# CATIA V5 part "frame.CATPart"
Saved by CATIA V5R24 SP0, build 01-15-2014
Part number: Frame
Bounding box of the stored display mesh (mm): x -211.5 to 30, y -33.991 to 33.991, z -18 to 268
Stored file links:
  D:\OneDrive\OneDrive - 한양대학교\문서\Teaching\2021\CAD\Final Exam\oscillation motion\frame.CATPart
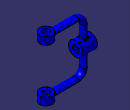
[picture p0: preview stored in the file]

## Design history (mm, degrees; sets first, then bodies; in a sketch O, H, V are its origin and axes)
Body1 (main body)
  Sketch1 on xy-plane, origin (0, 0, 0), H (1, 0, 0), V (0, 1, 0)
    circle A1 centre (0, 0) radius 16
    circle A2 centre (0, 0) radius 30
    radius A2 = 30
    radius A1 = 16
  Pad1: profile Sketch1, direction (0, 0, 1), length 18, mirrored extent
  Plane1: type Offset, RefPlane yz-plane, Offset 20, reversed
  Sketch2 on Plane1, origin (-20, 0, 0), H (0, 1, 0), V (0, 0, 1)
  Sketch3 on Plane1, origin (-20, 0, 0), H (0, 1, 0), V (0, 0, 1)
    ellipse A1 centre (0, 0) semi-axes 17.5, 11 rotation 180
    reference intersected line E1 through (0, 0) direction (-1, 0) from xy-plane
    distance E1 A1 = 11
    "Radius" A1 = 17.5
  Sketch4 on zx-plane, origin (0, 0, 0), H (-1, 0, 0), V (0, 0, 1)
    line L1 (20, 0) -> (141.5, 0)
    point P1 (20, 0)
    reference intersected line E1 through (20, 0) direction (0, -1) from Plane1
    arc A1 centre (141.5, 36) radius 36 from (141.5, 0) to (177.5, 36) ccw
    line L2 (177.5, 36) -> (177.5, 96)
    length L1 = 121.5
    radius A1 = 36
    length L2 = 60
    horizontal: L1 H
    coincidence: E1 P1, L1 H
    tangency: L2 A1
  Rib1: profile Sketch3, centre curve Sketch4
  Plane2: type Offset, RefPlane face of Rib1, Offset 29, reversed
  Sketch5 on zx-plane, origin (0, 0, 0), H (-1, 0, 0), V (0, 0, 1)
    line L1 (211.5, 109) -> (141.5, 109)
    line L2 (141.5, 109) -> (141.5, 91)
    line L3 (141.5, 91) -> (211.5, 91)
    line L4 (211.5, 91) -> (211.5, 109)
    reference projected line E1 (188.5, 96) -> (166.5, 96) from edge [face of Rib1 | face of Rib1]
    axis line L5 (150, 125) -> (200, 125)
    length L4 = 18
    length L3 = 70
    distance V L2 = 141.5
    distance E1 L3 = 5
    distance L5 L1 = 16
    horizontal: L1 H, L3 H, L5 H
    vertical: L2 V, L4 V
  Shaft1: profile Sketch5, axis Sketch5.L5, angle 360
  Mirror1: of Pad1, Rib1, about Plane2
  Fillet1: radius 4, on edge [face of Rib1 | face of Shaft1 from Sketch5.L3]; edge [face of Mirror1 | face of Mirror1]; edge [face of Mirror1 | face of Shaft1 from Sketch5.L3]; edge [face of Rib1 | face of Pad1 from Sketch1.A2]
